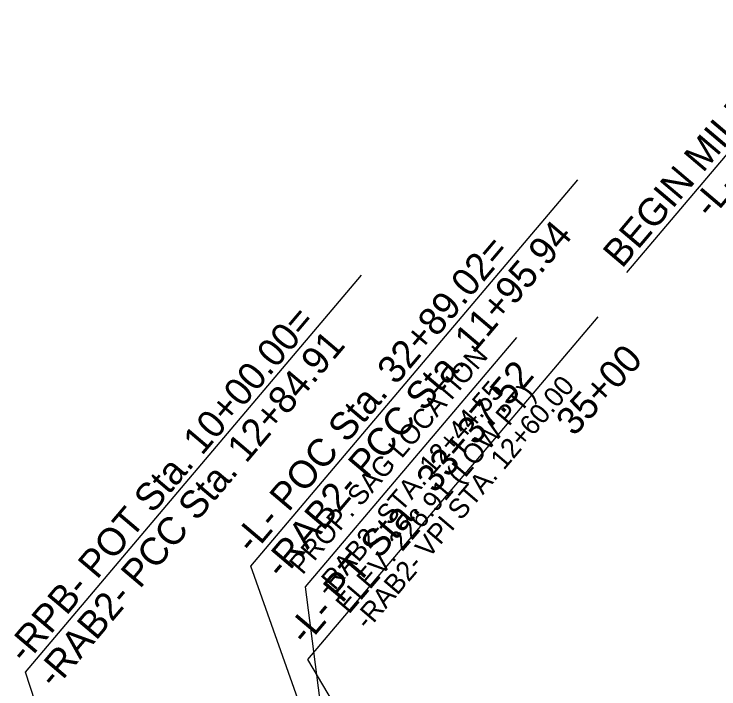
# Model space of a CAD drawing. Extents: x 1761082 to 1764358, y 421907 to 425434.
# Drawn here: x 1762626.7 to 1762805.2, y 423855.3 to 424026 of the extents above; entities that cross this region are included whole.
import ezdxf

# ---------------------------------------------------------------- set-up
doc = ezdxf.new("R2010")
doc.units = 0
for name, color, linetype in [('MARK HOOKS STRAIGHT RIGHT TURN ARROW CELL', 7, 'Continuous'), ('MARK UTURN ARROW CELL', 7, 'Continuous'), ('Scratch_Level_1', 7, 'Continuous')]:
    doc.layers.add(name, color=color, linetype=linetype)

msp = doc.modelspace()

# ---------------------------------------------------------------- linework, layer by layer
at = {"layer": 'MARK UTURN ARROW CELL'}
for points in [[(1763013.15, 423940.16), (1762869.88, 424064.58), (1762781.79, 423960.6)], [(1762717.14, 423800.32), (1762686.66, 423886.31), (1762769.46, 423984.05)], [(1762684.86, 423690.18), (1762629.61, 423859.52), (1762714.68, 423959.94)], [(1762753.43, 423774.41), (1762701.14, 423862.74), (1762774.59, 423949.45)]]:
    msp.add_lwpolyline(points, dxfattribs=at)
at = {"layer": 'Scratch_Level_1'}
msp.add_lwpolyline([(1762725.19, 423689.75), (1762700.56, 423881.1), (1762754, 423944.18)], dxfattribs=at)

# ---------------------------------------------------------------- texts
at = {"layer": 'MARK HOOKS STRAIGHT RIGHT TURN ARROW CELL'}
msp.add_text('35+00', height=7, rotation=47.5234, dxfattribs=at).set_placement((1762768.5, 423918.94))
at = {"layer": 'MARK UTURN ARROW CELL'}
for s, p in [('BEGIN MILLING/RESURFACING', (1762780.64, 423961.47)), ('-L- POC Sta.  36+60.00', (1762803.22, 423973.93)), ('-RAB2- PCC Sta. 11+95.94', (1762694.6, 423882.75)), ('-L- POC Sta. 32+89.02=', (1762687.12, 423889.09)), ('-RPB- POT Sta. 10+00.00=', (1762629.57, 423861.32)), ('-RAB2- PCC Sta. 12+84.91', (1762637.05, 423854.99)), ('-L- PT Sta.  33+37.52', (1762700.69, 423866))]:
    msp.add_text(s, height=7, rotation=49.7301, dxfattribs=at).set_placement(p)
at = {"layer": 'Scratch_Level_1'}
for s, p in [('PROP. SAG LOCATION', (1762699.78, 423883.94)), ('-RAB2- STA. 12+44.55', (1762706.44, 423878.3)), ('-RAB2- VPI STA. 12+60.00', (1762716.26, 423869.98)), ('ELEV. 226.91 (LOW PT)', (1762711.52, 423874))]:
    msp.add_text(s, height=5, rotation=49.5644, dxfattribs=at).set_placement(p)

doc.saveas('drawing.dxf')
